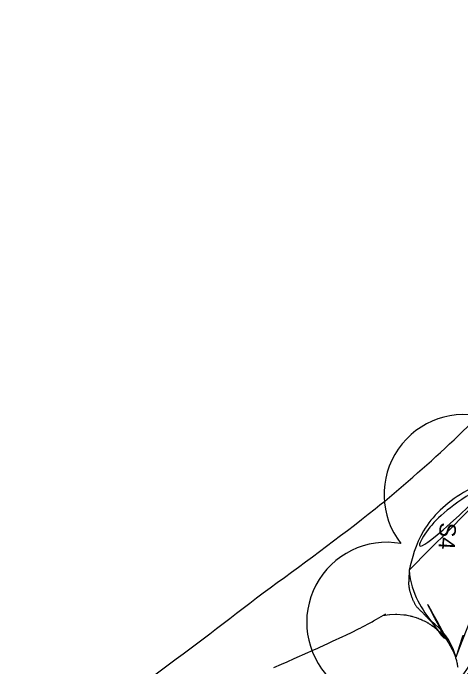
# Model space of a CAD drawing. Extents: x 0 to 512122, y 0 to 6212554.
# Drawn here: x 511640.46 to 511674.62, y 6211444.14 to 6211494.01 of the extents above; entities that cross this region are included whole.
import ezdxf

# ---------------------------------------------------------------- set-up
doc = ezdxf.new("R2010")
doc.units = 0
for name, color, linetype in [('_G3_engræsser', 7, 'Continuous'), ('_Paths', 7, 'Continuous'), ('_S4_Løvstikke', 7, 'Continuous'), ('Clouds', 7, 'Continuous'), ('TV_U_AFM_Symbl_Gul', 7, 'Continuous'), ('TV_U_LYS_Nyx330-Trafiksti-x2', 7, 'Continuous')]:
    doc.layers.add(name, color=color, linetype=linetype)

msp = doc.modelspace()

# ---------------------------------------------------------------- linework, layer by layer
at = {"layer": '_G3_engræsser'}
for centre, radius, start, end in [((511598.662, 6211541.423), 109.919, 309.16472, 317.01158), ((511525.583, 6211637.751), 230.797, 305.47664, 308.12804), ((511428.115, 6211746.745), 376.469, 304.81194, 307.93028)]:
    msp.add_arc(centre, radius, start, end, dxfattribs=at)
at = {"layer": '_Paths'}
for points, degree in [([(511640.462, 6211394.164), (511666.005, 6211408.809), (511672.517, 6211429.483), (511676.559, 6211451.282), (511690.481, 6211465.664), (511705.077, 6211478.474), (511709.825, 6211494.014), (511640.462, 6211394.164), (511709.825, 6211494.014)], 3), ([(511651.32, 6211395.399), (511670.02, 6211402.099), (511675.836, 6211429.41), (511675.931, 6211450.773), (511691.497, 6211463.947), (511708.899, 6211474.665), (511711.288, 6211488), (511712.286, 6211493.573)], 2)]:
    msp.add_open_spline(points, degree=degree, dxfattribs=at)
at = {"layer": '_S4_Løvstikke'}
msp.add_arc((511669.595, 6211443.718), 4.773, 16.2912, 55.4489, dxfattribs=at)
for points, degree in [([(511688.335, 6211469.331), (511679.63, 6211459.698), (511674.055, 6211456.91), (511671.464, 6211454.05), (511670.678, 6211451.524), (511688.335, 6211469.331), (511670.678, 6211451.524)], 3), ([(511674.265, 6211444.909), (511676.685, 6211451.489), (511680.723, 6211457.307), (511683.183, 6211459.963), (511683.585, 6211460.565), (511674.265, 6211444.909), (511683.585, 6211460.565)], 3), ([(511679.63, 6211459.698), (511677.85, 6211458.705), (511674.519, 6211457.738), (511671.372, 6211454.532), (511670.879, 6211452.394), (511670.678, 6211451.524)], 3), ([(511670.678, 6211451.524), (511670.646, 6211450.883), (511670.613, 6211450.241), (511670.793, 6211449.681)], 2), ([(511670.678, 6211451.524), (511670.793, 6211449.681), (511672.635, 6211447.286), (511674.265, 6211444.909), (511670.678, 6211451.524), (511674.265, 6211444.909)], 3), ([(511670.793, 6211449.681), (511671.041, 6211448.909), (511671.693, 6211448.291), (511672.302, 6211447.649)], 2), ([(511674.265, 6211444.909), (511674.439, 6211445.466), (511674.614, 6211446.024), (511674.793, 6211446.579)], 2), ([(511674.176, 6211445.057), (511674.206, 6211445.007), (511674.235, 6211444.958), (511674.265, 6211444.909)], 2)]:
    msp.add_open_spline(points, degree=degree, dxfattribs=at)
at = {"layer": 'Clouds'}
for centre, start, end in [((511674.856, 6211457.292), 72.8126, 217.8126), ((511668.957, 6211447.548), 79.802, 224.802)]:
    msp.add_arc(centre, 6.1, start, end, dxfattribs=at)
at = {"layer": 'TV_U_LYS_Nyx330-Trafiksti-x2'}
for points in [[(511660.361, 6211444.096), (511660.925, 6211444.347), (511661.356, 6211444.539), (511661.89, 6211444.777), (511662.931, 6211445.241), (511663.178, 6211445.351), (511663.264, 6211445.39), (511663.703, 6211445.585), (511663.809, 6211445.634), (511664.523, 6211445.962), (511664.821, 6211446.099), (511665.601, 6211446.458), (511665.83, 6211446.564), (511665.94, 6211446.614), (511666.229, 6211446.756), (511666.851, 6211447.064), (511666.937, 6211447.106), (511667.121, 6211447.203), (511667.157, 6211447.222), (511667.64, 6211447.477), (511667.837, 6211447.591), (511667.942, 6211447.651), (511668.173, 6211447.785), (511668.892, 6211448.2)], [(511668.664, 6211448.062), (511669.167, 6211448.14), (511669.184, 6211448.143), (511669.639, 6211448.163), (511669.741, 6211448.167), (511670.253, 6211448.128), (511670.325, 6211448.122), (511670.406, 6211448.105), (511670.494, 6211448.087), (511670.758, 6211448.033), (511670.786, 6211448.027), (511670.81, 6211448.022), (511670.886, 6211448.007), (511670.924, 6211447.999), (511671.094, 6211447.946), (511671.121, 6211447.937), (511671.127, 6211447.936), (511671.225, 6211447.905), (511671.242, 6211447.899), (511671.323, 6211447.868), (511671.347, 6211447.859), (511671.371, 6211447.849), (511671.444, 6211447.822), (511671.515, 6211447.795), (511671.525, 6211447.791), (511671.536, 6211447.786), (511671.557, 6211447.776), (511671.628, 6211447.743), (511671.693, 6211447.713), (511671.726, 6211447.697), (511671.819, 6211447.654), (511672.011, 6211447.548), (511672.032, 6211447.537), (511672.081, 6211447.51), (511672.108, 6211447.495), (511672.161, 6211447.461), (511672.206, 6211447.432), (511672.3, 6211447.372), (511672.387, 6211447.316), (511672.391, 6211447.313), (511672.41, 6211447.299), (511672.515, 6211447.22), (511672.517, 6211447.219), (511672.519, 6211447.217), (511672.601, 6211447.156), (511672.644, 6211447.123), (511672.655, 6211447.115), (511672.746, 6211447.037), (511672.768, 6211447.018), (511672.776, 6211447.011), (511672.782, 6211447.006), (511672.815, 6211446.978), (511672.91, 6211446.896), (511672.938, 6211446.868), (511672.999, 6211446.808), (511673.101, 6211446.706), (511673.149, 6211446.658), (511673.237, 6211446.558), (511673.299, 6211446.487), (511673.316, 6211446.467), (511673.371, 6211446.404), (511673.376, 6211446.397), (511673.415, 6211446.346), (511673.445, 6211446.307), (511673.485, 6211446.253), (511673.503, 6211446.23), (511673.546, 6211446.173), (511673.574, 6211446.136), (511673.675, 6211445.98), (511673.692, 6211445.954), (511673.752, 6211445.86), (511673.753, 6211445.859), (511673.756, 6211445.855), (511673.824, 6211445.734), (511673.834, 6211445.716), (511673.917, 6211445.567), (511673.918, 6211445.565), (511673.965, 6211445.465), (511673.983, 6211445.426), (511674.009, 6211445.37), (511674.057, 6211445.267), (511674.066, 6211445.244), (511674.078, 6211445.213), (511674.106, 6211445.14), (511674.147, 6211445.033), (511674.174, 6211444.964), (511674.199, 6211444.883), (511674.213, 6211444.84), (511674.236, 6211444.766), (511674.248, 6211444.727), (511674.267, 6211444.666), (511674.27, 6211444.658), (511674.281, 6211444.611), (511674.291, 6211444.571), (511674.309, 6211444.493), (511674.332, 6211444.396), (511674.343, 6211444.351), (511674.369, 6211444.166), (511674.375, 6211444.121)]]:
    msp.add_lwpolyline(points, dxfattribs=at)

# ---------------------------------------------------------------- texts
at = {"layer": 'TV_U_AFM_Symbl_Gul'}
msp.add_text('S4', height=1.25, rotation=266.685, dxfattribs=at).set_placement((511673.016, 6211455.185))

doc.saveas('drawing.dxf')
